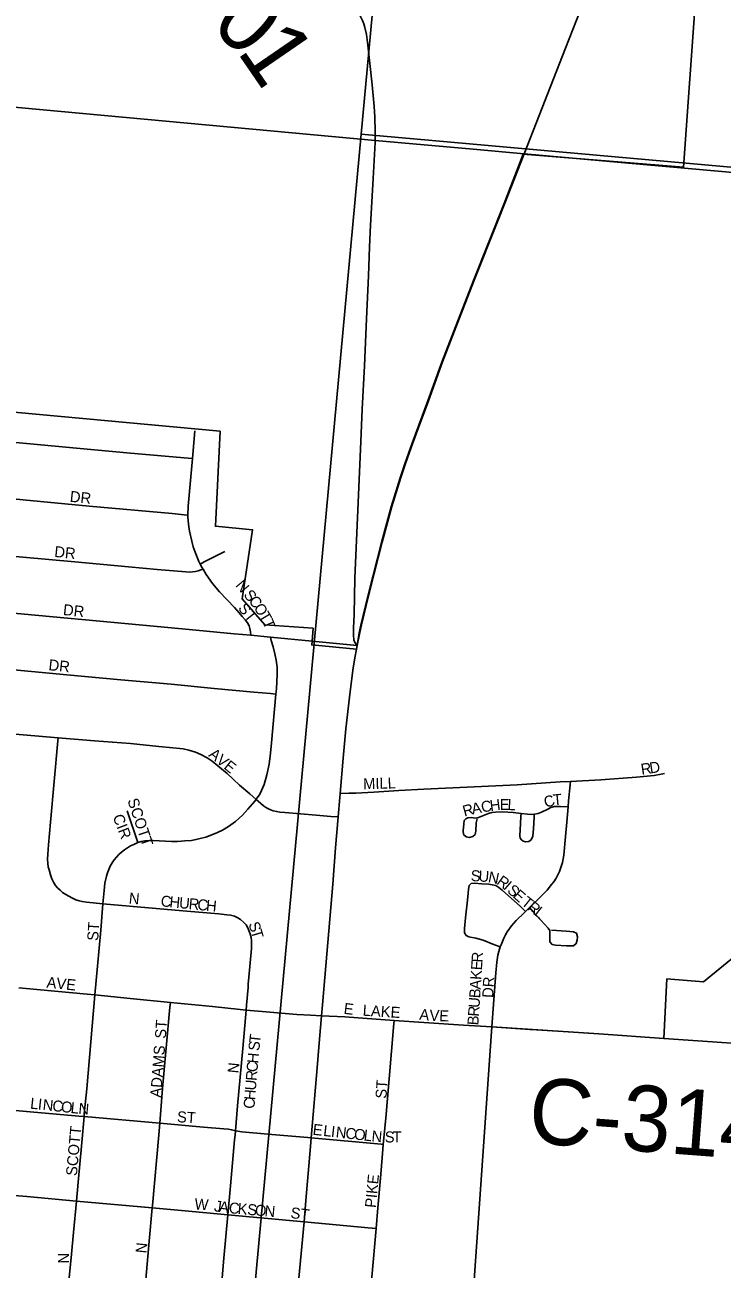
# Model space of a CAD drawing. Extents: x 1410790 to 1770854, y 566777 to 831614.
# Drawn here: x 1539653 to 1542824, y 709330 to 714986 of the extents above; entities that cross this region are included whole.
import ezdxf

# ---------------------------------------------------------------- set-up
doc = ezdxf.new("R2010")
doc.units = 0
for name, color, linetype in [('GM_X_City_Street', 7, 'Continuous'), ('GM_X_City_Street_Text', 7, 'Continuous'), ('GM_X_Corporation', 7, 'Continuous'), ('GM_X_County_Road', 7, 'Continuous'), ('GM_X_County_Road_Text', 7, 'Continuous'), ('GM_X_Section', 7, 'Continuous'), ('GM_X_State_Route', 7, 'Continuous'), ('GM_X_Township', 7, 'Continuous'), ('GM_X_Township_Subdivision', 7, 'Continuous')]:
    doc.layers.add(name, color=color, linetype=linetype)

msp = doc.modelspace()

# ---------------------------------------------------------------- linework, layer by layer
at = {"layer": 'GM_X_City_Street'}
for points in [[(1539135.9, 713131.8), (1539676.8, 713081), (1539888.9, 713061.2), (1540133.3, 713038.6), (1540395.3, 713016.5), (1540415.1, 713014.8)], [(1540415.1, 713014.8), (1540425.9, 713140.1)], [(1540395, 712757.3), (1540396.3, 712797.7), (1540415.1, 713014.8)], [(1539155, 712871.9), (1539422.4, 712848.5), (1539946.1, 712798), (1540322.7, 712764.1), (1540378.4, 712758.9), (1540395, 712757.3)], [(1540450.7, 712534.9), (1540444.1, 712547), (1540427.7, 712588.6), (1540419, 712612.7), (1540412.1, 712638.4), (1540402.2, 712683.6), (1540396.9, 712715.9), (1540394.7, 712748.6), (1540395, 712757.3)], [(1539328.8, 712594.8), (1539422.9, 712585.8), (1539879.9, 712544.8), (1540124.6, 712522.3), (1540255.1, 712509.4), (1540385.7, 712499.1), (1540402, 712498.4), (1540416.2, 712499.2), (1540429.7, 712500.9), (1540441.6, 712503.7), (1540454, 712507.7), (1540464, 712510.9)], [(1540450.7, 712534.9), (1540468.7, 712544.3), (1540504.8, 712563.1), (1540562.5, 712591.2)], [(1540464, 712510.9), (1540459.7, 712518.2), (1540450.7, 712534.9)], [(1540681.1, 712210.7), (1540678.9, 712226.3), (1540676.8, 712241.6), (1540672.7, 712253.9), (1540665.2, 712267), (1540655.2, 712280.8), (1540641.4, 712295.9), (1540627.8, 712312.4), (1540606.6, 712337.3), (1540539.1, 712409.1), (1540507.3, 712446.6), (1540477.9, 712487.5), (1540464, 712510.9)], [(1539503.7, 712320.7), (1540255.2, 712251.2), (1540401, 712237.4), (1540605.9, 712217.8), (1540681.1, 712210.7)], [(1540681.1, 712210.7), (1540770.1, 712202)], [(1540770.1, 712202), (1540959.9, 712183.7)], [(1540795.1, 711943.4), (1540797.3, 711967.7), (1540800.9, 712033.3), (1540800.2, 712066), (1540796.7, 712097.9), (1540790.4, 712127.3), (1540782.3, 712158.1), (1540774.1, 712187.5), (1540770.1, 712202)], [(1539521.5, 712061.4), (1539844.3, 712031.6), (1540089.4, 712008), (1540318.3, 711988.6), (1540514.2, 711969), (1540694, 711952.7), (1540770.4, 711945.8), (1540795.1, 711943.4)], [(1540704.6, 711464.9), (1540708.8, 711470.6), (1540719.7, 711486), (1540729.7, 711504.8), (1540740.9, 711533), (1540754.1, 711576.8), (1540764.7, 711625.1), (1540771, 711675.2), (1540774.9, 711722.3), (1540795.1, 711943.4)], [(1539495.5, 711773.3), (1539593.3, 711763.2), (1539804.2, 711745.4)], [(1540008.4, 710990.5), (1539934, 710997.3), (1539914.4, 711000.9), (1539900.2, 711004.3), (1539885.7, 711008.6), (1539869.6, 711015.5), (1539853.3, 711024.6), (1539839, 711032.7), (1539825.2, 711041.7), (1539813.2, 711051.5), (1539802.5, 711062.3), (1539792.8, 711073.5), (1539783.7, 711089.1), (1539776.2, 711103.6), (1539769.7, 711121.3), (1539763.3, 711143.9), (1539760, 711158.4), (1539758.4, 711175), (1539756.8, 711193.3), (1539757.4, 711216.4), (1539761.1, 711258.8), (1539770.2, 711361.9), (1539803, 711731.8), (1539804.2, 711745.4)], [(1539804.2, 711745.4), (1539969.4, 711731.6), (1540133.1, 711718.5), (1540263.3, 711704.7), (1540278.9, 711703.9), (1540310.4, 711701.2), (1540374, 711694.1), (1540399.2, 711689), (1540429.6, 711679.4), (1540453.9, 711669), (1540481.7, 711654.2), (1540505.1, 711638.6), (1540531.1, 711617.8), (1540572.8, 711582.2), (1540630.1, 711530.1), (1540676.8, 711489.9), (1540704.6, 711464.9)], [(1541087.1, 711491.4), (1541126, 711492.5), (1541158.7, 711493.4), (1541240.3, 711497.6), (1541354.3, 711504.7), (1541468.4, 711511.2), (1541664.3, 711519.7), (1541892.8, 711531.5), (1542088.5, 711544), (1542134.4, 711546.3)], [(1542123.8, 711430.8), (1542125.9, 711458.8), (1542132.9, 711531), (1542134.4, 711546.3)], [(1542134.4, 711546.3), (1542272.3, 711553.2)], [(1542272.3, 711553.2), (1542272.5, 711553.2), (1542434.4, 711565.4), (1542515, 711573.8), (1542547, 711579), (1542562.6, 711583.2)], [(1540166.7, 711268.8), (1540182.3, 711273.7), (1540198.6, 711276.2), (1540220.5, 711278.1), (1540237.4, 711278.1), (1540320, 711273.7), (1540347.6, 711273.7), (1540380.8, 711276.2), (1540410.9, 711278.7), (1540431.5, 711281.8), (1540450.3, 711286.8), (1540476.6, 711293.7), (1540503.6, 711303.1), (1540529.2, 711313.8), (1540551.8, 711325.7), (1540580, 711342), (1540611.3, 711364.5), (1540642.6, 711393.3), (1540667.4, 711419.7), (1540689.3, 711444.1), (1540704.6, 711464.9)], [(1540704.6, 711464.9), (1540725.8, 711446.1), (1540738.6, 711435.8), (1540752.2, 711426.7), (1540766.8, 711419.1), (1540782.1, 711413.3), (1540799.1, 711409.1), (1540813.6, 711407.4), (1540835.5, 711404.9), (1540977.8, 711393), (1541044.3, 711387.7), (1541078, 711385)], [(1540166.7, 711268.8), (1540118.9, 711413.1)], [(1541710, 711376.4), (1541706.4, 711358.3), (1541704.2, 711320), (1541701.6, 711305.9), (1541691.3, 711296), (1541675.8, 711291.8), (1541659.8, 711294.7), (1541648.1, 711305.5), (1541646.2, 711321.4), (1541649.1, 711353.9), (1541651, 711368.9), (1541659.3, 711376.4), (1541668.6, 711381.2), (1541684, 711382.1), (1541699.8, 711379.7), (1541715.7, 711382.6), (1541731.2, 711387.9), (1541761.3, 711400.5), (1541776.8, 711405.1), (1541793, 711407.1), (1541825.6, 711407.7), (1541874.4, 711404.9), (1541910.1, 711400.8)], [(1541910.1, 711400.8), (1541909.1, 711386.5), (1541906.8, 711355.9), (1541903.8, 711299.7), (1541905.5, 711289.2), (1541912.1, 711280.4), (1541919.6, 711275.5), (1541929.8, 711272), (1541945.6, 711274.2), (1541956.2, 711281.7), (1541963.2, 711297.1), (1541966.9, 711330.7), (1541969.4, 711383), (1541970.1, 711397.3)], [(1541910.1, 711400.8), (1541939.3, 711397.3), (1541955.6, 711396.4), (1541970.1, 711397.3)], [(1541947.9, 710972.7), (1541981.3, 711005.4), (1542028, 711052.8), (1542048.8, 711078.1), (1542059.2, 711089.9), (1542069.5, 711106.8), (1542085.5, 711137.3), (1542099.1, 711177.7), (1542105.2, 711211), (1542112.2, 711295.7), (1542118.8, 711360.9), (1542123.8, 711430.8)], [(1541970.1, 711397.3), (1541971.7, 711397.4), (1541987.5, 711400.9), (1542002.7, 711406.6), (1542032.4, 711420.3), (1542045.6, 711427.5), (1542062.8, 711432.8), (1542090.1, 711431.9), (1542123.8, 711430.8)], [(1540008.4, 710990.5), (1540013.5, 711050.9), (1540017.6, 711083.6), (1540024.2, 711115.8), (1540028.9, 711131.6), (1540034.8, 711146.9), (1540041.9, 711161.8), (1540050.2, 711176), (1540059.5, 711189.6), (1540069.8, 711202.4), (1540081.1, 711214.4), (1540093.3, 711225.4), (1540106.2, 711235.7), (1540119.8, 711245), (1540133.9, 711253.3), (1540148.7, 711260.5), (1540166.7, 711268.8)], [(1541815.3, 710793.9), (1541782.1, 710807), (1541737.9, 710824.6), (1541704.4, 710834.2), (1541672.2, 710839.6), (1541660.5, 710845.6), (1541653.3, 710858.8), (1541653, 710877.4), (1541657.3, 710925.9), (1541665.7, 711006.9), (1541669.4, 711039.3), (1541670.6, 711057.4), (1541674, 711073.2), (1541682.6, 711081.8), (1541698.7, 711083.3), (1541730.1, 711081.1), (1541763.6, 711079), (1541779.3, 711077.2), (1541794.7, 711074), (1541808.6, 711065), (1541824.3, 711051.9), (1541906.7, 710977.3), (1541930.6, 710955.6)], [(1539971.7, 710576.2), (1539983, 710706.6), (1539998.4, 710870.5), (1540008.4, 710990.5)], [(1540659.1, 710507.2), (1540660.9, 710528.9), (1540668.3, 710609), (1540669.3, 710624.8), (1540672.3, 710657.4), (1540684.1, 710786.3), (1540684.4, 710804.8), (1540684.3, 710821.2), (1540682.2, 710837.5), (1540678.3, 710853.4), (1540672.3, 710868.7), (1540667.5, 710880.8), (1540659.4, 710894.7), (1540648.1, 710907.1), (1540634.2, 710918.4), (1540621.3, 710927), (1540607.4, 710933.4), (1540589.1, 710938.2), (1540571.4, 710940.4), (1540535.7, 710943.9), (1540372.1, 710958.1), (1540008.4, 710990.5)], [(1541815.3, 710793.9), (1541818.9, 710804.4), (1541831.7, 710834.6), (1541839.1, 710849.2), (1541847.4, 710863.3), (1541866.6, 710889.9), (1541888.2, 710914.5), (1541923.4, 710948.8), (1541930.6, 710955.6)], [(1541930.6, 710955.6), (1541947.9, 710972.7)], [(1541947.9, 710972.7), (1541964.9, 710953.8), (1541977.6, 710939.8), (1542000.6, 710915.8), (1542032.9, 710879.7), (1542040.4, 710868.4), (1542040.8, 710849.6), (1542040.2, 710833.3), (1542041.1, 710817), (1542051.3, 710805.6), (1542067.2, 710802.3), (1542116, 710798.8), (1542132, 710798.5), (1542148.2, 710799.1), (1542160.6, 710809.2), (1542165.4, 710824.6), (1542166.7, 710840.8), (1542162.1, 710856), (1542148.2, 710863.5), (1542115.7, 710866.1), (1542048.4, 710870.8)], [(1541776.6, 710430.3), (1541795, 710676.1), (1541799.5, 710725.1), (1541804.7, 710757.4), (1541808.4, 710773.3), (1541815.3, 710793.9)], [(1539625.6, 710608.3), (1539643, 710606.5), (1539936.7, 710579.9), (1539971.7, 710576.2)], [(1539922.5, 710022.7), (1539923.5, 710035.5), (1539934.6, 710149.7), (1539971.7, 710576.2)], [(1539971.7, 710576.2), (1540132.3, 710560), (1540315.1, 710541.8)], [(1540267, 709992.5), (1540279.9, 710149.9), (1540312.9, 710519.6), (1540315.1, 710541.8)], [(1540315.1, 710541.8), (1540507.2, 710522.7), (1540632.6, 710509.9), (1540659.1, 710507.2)], [(1540611.1, 709958.5), (1540621.1, 710071.4), (1540644.3, 710333.1), (1540659.1, 710507.2)], [(1540659.1, 710507.2), (1540733.3, 710500.2), (1540889.6, 710487.6), (1540952.1, 710483.8), (1541002.4, 710480.4)], [(1541002.4, 710480.4), (1541108.6, 710476.3), (1541332.8, 710459.9)], [(1541283.6, 709896.1), (1541294.4, 710015.2), (1541309.5, 710194.8), (1541331.5, 710445.5), (1541332.8, 710459.9)], [(1541332.8, 710459.9), (1541468.5, 710450), (1541648.6, 710438.5), (1541776.6, 710430.3)], [(1541776.6, 710430.3), (1541950.1, 710418.8), (1541955.7, 710418.5)], [(1539575.5, 710053.6), (1539898.2, 710024.8), (1539922.5, 710022.7)], [(1539887.7, 709638.8), (1539895.6, 709724.7), (1539911.7, 709904.5), (1539922.5, 710022.7)], [(1539922.5, 710022.7), (1540267, 709992.5)], [(1540232.4, 709607.7), (1540233.3, 709618), (1540262.8, 709940.5), (1540267, 709992.5)], [(1540267, 709992.5), (1540466.2, 709975.1), (1540558.3, 709967.1), (1540579.1, 709965.2), (1540593.8, 709962.8), (1540611.1, 709958.5)], [(1540576, 709576.2), (1540588, 709708.7), (1540607.4, 709916.5), (1540609.4, 709938.9), (1540611.1, 709958.5)], [(1540611.1, 709958.5), (1540622.4, 709956.1), (1540639.8, 709953.6), (1540758.8, 709942.6), (1540940, 709927.5), (1540955.5, 709926.2)], [(1540955.5, 709926.2), (1541273.1, 709897), (1541283.6, 709896.1)], [(1541250.9, 709513.9), (1541258.4, 709607.7), (1541270.4, 709742.5), (1541279.9, 709855.3), (1541283.6, 709896.1)], [(1539541.2, 709669.7), (1539549.9, 709668.9), (1539662.3, 709659.1), (1539887.7, 709638.8)], [(1539850.4, 709243.8), (1539865.1, 709398.1), (1539874.4, 709495.6), (1539887.7, 709638.8)], [(1539887.7, 709638.8), (1540232.4, 709607.7)], [(1540197, 709213.3), (1540218.6, 709456.1), (1540232.4, 709607.7)], [(1540232.4, 709607.7), (1540365.4, 709595.7), (1540576, 709576.2)], [(1540541, 709182.2), (1540558.2, 709378.9), (1540576, 709576.2)], [(1540576, 709576.2), (1540922.9, 709544.1)], [(1540922.9, 709544.1), (1541215.3, 709516.7), (1541250.9, 709513.9)], [(1541215.9, 709117.3), (1541231.4, 709292.2), (1541250.9, 709513.9)]]:
    msp.add_lwpolyline(points, dxfattribs=at)
at = {"layer": 'GM_X_Corporation'}
for points in [[(1539191.9, 713263.2), (1540541.3, 713138.1), (1540519.8, 712706.3), (1540688.9, 712690.7), (1540641.3, 712377.3), (1540745.4, 712259), (1540963.8, 712243), (1540959.9, 712183.8), (1540958.4, 712166.9), (1541161.3, 712147.6), (1541164.5, 712164.5), (1541173.2, 712221.9), (1541180.7, 712256.3), (1541202.2, 712345.5), (1541218.9, 712413), (1541274.8, 712632), (1541319.8, 712794.6), (1541360.3, 712926.9), (1541381.5, 712990.5), (1541407.7, 713063.6), (1541430.3, 713125.4), (1541485.7, 713276), (1541543.5, 713435.7), (1541550.1, 713452.8), (1541604.1, 713594.1), (1541693.5, 713823), (1541832.7, 714174.4), (1541920.3, 714397.5), (1542648.4, 714338.8), (1542734.1, 715524.6)], [(1543161.3, 710979.8), (1542739.1, 710635.3), (1542573.3, 710648.9), (1542559, 710377.2), (1542264.4, 710398.4), (1541776.6, 710430.3), (1541657, 708714.2), (1541540.7, 708633.5), (1541187.7, 708363.9), (1540971.5, 708283.5), (1540522.4, 707554.8), (1540365.5, 705718.8)]]:
    msp.add_lwpolyline(points, dxfattribs=at)
at = {"layer": 'GM_X_County_Road'}
for points in [[(1541244.9, 714567.4), (1541241.9, 714615.4), (1541232.5, 714713.4), (1541213.7, 714892.8), (1541206.9, 714941.9), (1541199.4, 714974.3), (1541194.3, 714990.1), (1541188.2, 715005.7), (1541181.1, 715020.8), (1541173.1, 715035.4), (1541154.8, 715063.2), (1541133.9, 715089), (1541099.5, 715124.6), (1540967.5, 715247.7), (1540859.4, 715348), (1540739.1, 715459.4), (1540487.8, 715694.7), (1540307.4, 715861.7), (1540187.5, 715973.5), (1540080.5, 716074.9), (1539960.9, 716187.1), (1539844.9, 716296.2)], [(1541164.5, 712164.5), (1541154.5, 712177.4), (1541152, 712182), (1541150.5, 712185.6), (1541149.6, 712189.9), (1541148.7, 712195), (1541147.7, 712207.2), (1541148.1, 712243), (1541150.7, 712306), (1541154, 712469.9), (1541168.4, 712813.8), (1541181.3, 713092), (1541188, 713239.5), (1541197.5, 713435.9), (1541206.4, 713648.9), (1541216, 713845.3), (1541221.3, 713976.4), (1541225.9, 714074.6), (1541238, 714287.3), (1541246.2, 714451), (1541246.4, 714460.7), (1541247.1, 714500.4), (1541244.9, 714566.1), (1541244.9, 714567.4)], [(1541955.7, 710418.5), (1542125.6, 710407.5), (1542264.4, 710398.4), (1542559.1, 710377.2), (1542714, 710366.8)], [(1542714, 710366.8), (1542736.6, 710365.2), (1542953.8, 710350), (1543066.7, 710340.4), (1543140.5, 710335.8)]]:
    msp.add_lwpolyline(points, dxfattribs=at)
at = {"layer": 'GM_X_Section'}
for points in [[(1541667.5, 719721.9), (1546971.8, 719240), (1546517.1, 714013.2), (1541182.8, 714489.6)], [(1541182.8, 714489.6), (1546517.1, 714013.2), (1545998.2, 708649.6), (1540688, 709135.5)]]:
    msp.add_lwpolyline(points, close=True, dxfattribs=at)
at = {"layer": 'GM_X_State_Route'}
for points in [[(1541923.6, 714399.4), (1542112.3, 714879.6), (1542245.6, 715220.1), (1542375.8, 715549.9)], [(1540898.9, 709288.5), (1540922.9, 709544.1), (1540930.4, 709641), (1540952.1, 709886.2), (1540955.5, 709926.2), (1540984.4, 710262.5), (1540987.1, 710300.6), (1540993.5, 710375.3), (1541002.4, 710480.4), (1541006.8, 710530.7), (1541017.5, 710654.9), (1541053.9, 711080.2), (1541066.2, 711243.9), (1541078, 711385), (1541085.5, 711472.9), (1541087.1, 711491.4), (1541100.7, 711652.8), (1541112.5, 711785.1), (1541129.2, 711930), (1541145.4, 712052.9), (1541154, 712108.3), (1541161.3, 712147.6), (1541162.9, 712156.1), (1541164.5, 712164.5), (1541176.3, 712223.3), (1541183.8, 712257.7), (1541205.3, 712346.9), (1541222, 712414.4), (1541277.9, 712633.5), (1541322.9, 712796), (1541363.4, 712928.3), (1541384.5, 712991.9), (1541410.7, 713065), (1541433.4, 713126.8), (1541488.7, 713277.4), (1541546.6, 713437.2), (1541553.2, 713454.2), (1541607.2, 713595.5), (1541696.6, 713824.5), (1541803.6, 714094.7), (1541835.7, 714175.9), (1541923.4, 714398.9), (1541923.6, 714399.4)]]:
    msp.add_lwpolyline(points, dxfattribs=at)
at = {"layer": 'GM_X_Township'}
for points in [[(1536109.9, 720210.8), (1535643.5, 714974.4), (1536009.5, 714944), (1541246.4, 714460.7), (1541691.9, 714420.1), (1541923.4, 714398.9), (1548437.3, 713818.3), (1549151.2, 713753.6), (1551760.4, 713504.3), (1552475.2, 713454.2), (1554274.2, 713261.1), (1561321.7, 712527.7), (1562336.2, 712409.9), (1567635.1, 711954), (1567699, 712623.5), (1567713.4, 712780.3), (1567736.3, 713023.8), (1567847.7, 714189.3), (1568119.6, 717279)], [(1548437.3, 713818.3), (1541923.4, 714398.9), (1541691.9, 714420.1), (1541246.4, 714460.7), (1536009.5, 714944), (1535643.5, 714974.4), (1535639.2, 714824.7), (1535640.1, 714809), (1535640.2, 714776.6), (1535636.6, 714711.5), (1535629.3, 714618.5), (1535628.9, 714613.7), (1535608.8, 714385.7), (1535595.7, 714239.1), (1535574.8, 713994.5), (1535556.5, 713782.6), (1535536.5, 713537.9), (1535521.2, 713351.3), (1535519.7, 713326.1), (1535517.2, 713301.6), (1535471.8, 712844), (1535407.5, 712209), (1535086.4, 708725.9), (1534170.1, 699005.2)]]:
    msp.add_lwpolyline(points, dxfattribs=at)
at = {"layer": 'GM_X_Township_Subdivision'}
msp.add_lwpolyline([(1540959.9, 712183.7), (1541164.5, 712164.5)], dxfattribs=at)

# ---------------------------------------------------------------- texts
at = {"layer": 'GM_X_City_Street_Text'}
for s, rotation, p in [('DR', 353.994, (1539856, 712818.1)), ('DR', 353.9946, (1539785.6, 712567.3)), ('N', 309.7916, (1540608.8, 712436.8)), ('S', 309.7776, (1540645.4, 712392.9)), ('DR', 353.994, (1539825.2, 712303.3)), ('ST', 308.658, (1540620.2, 712332.7)), ('C', 309.7871, (1540668, 712365.8)), ('O', 302.5383, (1540692.3, 712336.7)), ('T', 300.699, (1540715.8, 712300)), ('T', 293.1663, (1540733, 712271.3)), ('DR', 353.994, (1539759.2, 712052.5)), ('A', 321.0774, (1540485.8, 711663.2)), ('V', 321.0774, (1540520, 711635.6)), ('E', 321.4691, (1540554.5, 711607.7)), ('R', 8.3585, (1542458.5, 711576.6)), ('D', 8.3357, (1542497.7, 711582.4)), ('MILL', 1.6902, (1541192.4, 711510.7)), ('T', 5.4999, (1542057.6, 711437.2)), ('SCOTT', 288.435, (1540119.2, 711460.9)), ('R', 15.515, (1541652.4, 711386.2)), ('A', 10.9285, (1541689.6, 711396.6)), ('C', 9.638, (1541732.5, 711404.8)), ('H', 7.1209, (1541770.9, 711411.4)), ('E', 0.2732, (1541813, 711416.7)), ('L', 356.6103, (1541847.4, 711416.9)), ('C', 17.3598, (1542022.5, 711426)), ('CIR', 290.8577, (1540051.9, 711386.7)), ('S', 358.0053, (1541680.6, 711093.4)), ('U', 356.0405, (1541715.3, 711092.2)), ('N', 348.5808, (1541757.5, 711089.4)), ('R', 323.5673, (1541795.4, 711083)), ('I', 319.2849, (1541826.5, 711060.1)), ('N', 354.2927, (1540124.4, 710992.1)), ('S', 318.7023, (1541843.1, 711045.8)), ('E', 318.6809, (1541869.5, 711022.6)), ('C', 354.4791, (1540269.6, 710978.9)), ('H', 354.4964, (1540309, 710975.1)), ('U', 354.484, (1540352.8, 710970.9)), ('R', 354.5113, (1540396.6, 710966.6)), ('C', 354.4791, (1540436.1, 710962.8)), ('H', 354.4904, (1540475.5, 710959)), ('T', 320.9732, (1541907.7, 710989.4)), ('R', 321.9066, (1541935.7, 710966.7)), ('L', 321.9386, (1541966.9, 710942.2)), ('ST', 86.4254, (1539986.5, 710820.5)), ('S', 290.0508, (1540669, 710898.3)), ('T', 286.4427, (1540680.8, 710866.1)), ('R', 86.257, (1541734.2, 710722.2)), ('E', 86.2686, (1541731.9, 710687.1)), ('AVE', 354.0895, (1539750.4, 710609.3)), ('A', 86.2601, (1541726.2, 710599.3)), ('K', 86.2773, (1541729.1, 710643.2)), ('DR', 86.989, (1541783, 710561.5)), ('B', 86.2721, (1541723.6, 710559.8)), ('E', 352.88, (1541101.4, 710490.5)), ('LAKE', 356.3452, (1541188.8, 710481.7)), ('U', 86.2601, (1541720.8, 710515.8)), ('A', 353.9567, (1541445.8, 710463.9)), ('V', 357.3132, (1541492.7, 710459)), ('E', 357.6181, (1541537, 710456.9)), ('B', 86.2691, (1541715.6, 710436.8)), ('R', 86.2721, (1541718.2, 710476.3)), ('ST', 86.4186, (1540294.5, 710376.1)), ('S', 84.2269, (1540719.1, 710319.7)), ('T', 83.441, (1540722.6, 710354.5)), ('ADAMS', 85.4263, (1540272.5, 710107.9)), ('H', 84.9006, (1540713.9, 710262.9)), ('N', 84.2937, (1540624.5, 710218.1)), ('C', 85.2585, (1540710.7, 710223.5)), ('R', 85.3069, (1540707.4, 710184)), ('ST', 86.4254, (1541297.7, 710103.3)), ('H', 85.3135, (1540700.2, 710096.3)), ('U', 85.3135, (1540703.8, 710140.2)), ('L', 353.8966, (1539675.7, 710059.3)), ('I', 353.8957, (1539710.7, 710055.5)), ('N', 353.8903, (1539732.5, 710053.2)), ('C', 353.8931, (1539776.3, 710048.5)), ('O', 353.9093, (1539815.7, 710044.3)), ('L', 353.8966, (1539859.4, 710039.6)), ('N', 354.778, (1539895.3, 710035.8)), ('C', 85.3069, (1540697, 710056.9)), ('ST', 356.4254, (1540344, 709997.7)), ('SCOTT', 84.8058, (1539889.7, 709751.6)), ('E', 353.5934, (1540960.5, 709940.5)), ('L', 353.6206, (1541008.6, 709935.1)), ('I', 353.5609, (1541043.6, 709931.2)), ('N', 353.6158, (1541065.5, 709928.7)), ('C', 353.5995, (1541109.2, 709923.8)), ('O', 353.6097, (1541148.6, 709919.4)), ('L', 353.5934, (1541192.3, 709914.5)), ('N', 354.4964, (1541228.2, 709910.5)), ('S', 359.7191, (1541290.1, 709905.5)), ('T', 359.9956, (1541325.6, 709905.3)), ('PIKE', 84.4277, (1541249.3, 709606.4)), ('W', 355.6039, (1540423.4, 709601.7)), ('J', 352.4602, (1540511.9, 709592.9)), ('A', 352.831, (1540534.1, 709589.9)), ('C', 354.6319, (1540579.4, 709584.2)), ('K', 355.0715, (1540619.3, 709580.5)), ('S', 355.0764, (1540663.1, 709576.7)), ('O', 355.0715, (1540698.2, 709573.7)), ('N', 355.0766, (1540742, 709569.9)), ('ST', 352.3949, (1540859.5, 709562.1)), ('N', 90, (1539854.5, 709354.7)), ('N', 84.2916, (1540206.5, 709399.7))]:
    msp.add_text(s, height=50, rotation=rotation, dxfattribs=at).set_placement(p)
at = {"layer": 'GM_X_County_Road_Text'}
for s, rotation, p in [('0', 316.7597, (1540490.9, 714979.3)), ('1', 304.4796, (1540614.5, 714865.6)), ('C-314', 355.6397, (1541937.4, 709904.8))]:
    msp.add_text(s, height=300, rotation=rotation, dxfattribs=at).set_placement(p)

doc.saveas('drawing.dxf')
